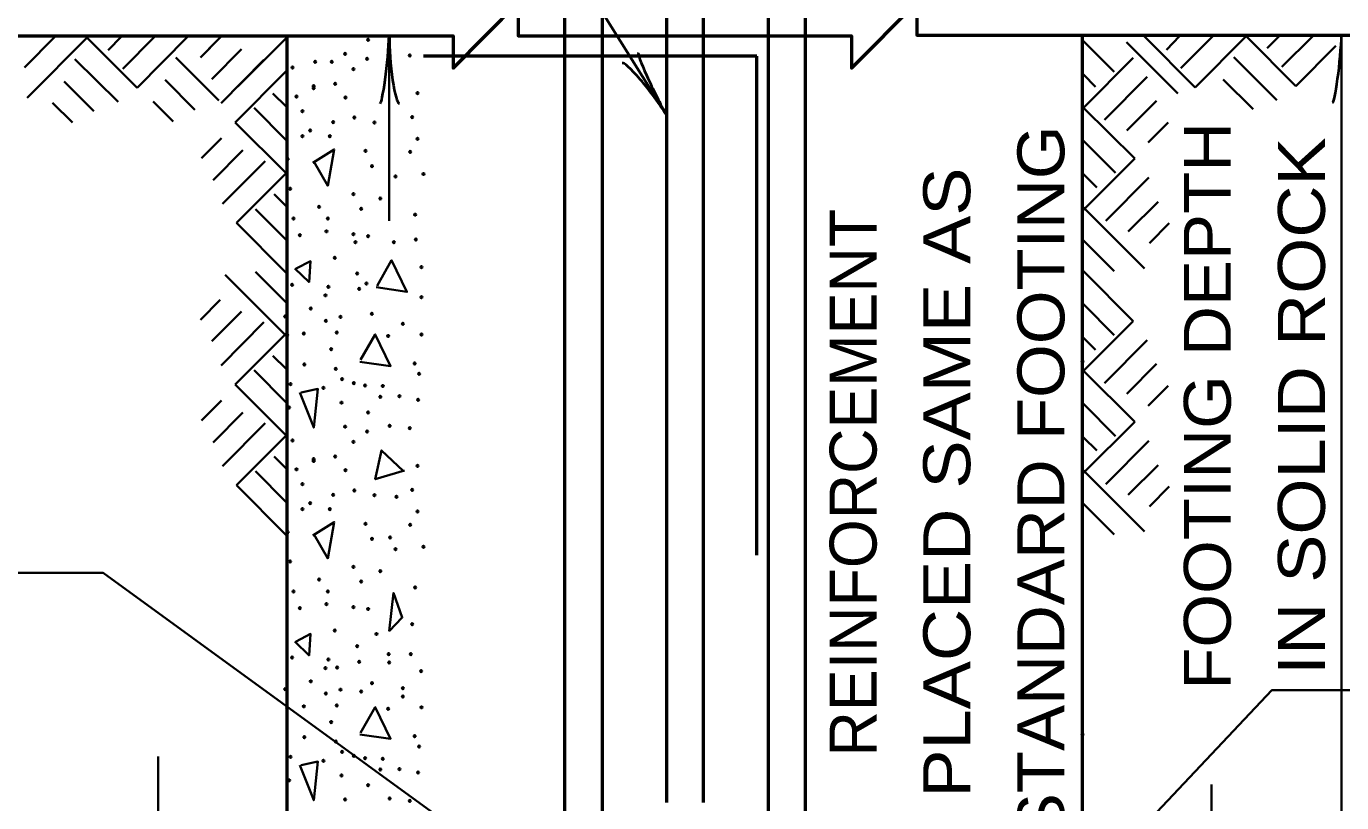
# Model space of a CAD drawing. Extents: x -39 to 816, y -16 to 528.
# Drawn here: x 422.4 to 490.2, y 435.9 to 475.9 of the extents above; entities that cross this region are included whole.
import ezdxf
from ezdxf.enums import TextEntityAlignment as Align

# ---------------------------------------------------------------- set-up
doc = ezdxf.new("R2010")
doc.units = 0
doc.header["$LTSCALE"] = 0.97
doc.layers.add('1', color=7, linetype='Continuous', lineweight=35)

msp = doc.modelspace()

# ---------------------------------------------------------------- linework, layer by layer
at = {"layer": '1', "lineweight": 53}
for p, q in [((450.1526, 483.0279), (450.1526, 432.0759)), ((452.0966, 483.0279), (452.0966, 432.0759)), ((460.6406, 483.0279), (460.6406, 432.0759)), ((462.5606, 483.0279), (462.5606, 432.0759)), ((455.4086, 478.2519), (455.4086, 435.8919)), ((457.3046, 478.2519), (457.3046, 435.8919)), ((435.8726, 423.9879), (435.8726, 475.3959)), ((476.8406, 423.9879), (476.8406, 475.4199)), ((460.0608, 474.3369), (442.9008, 474.3369)), ((460.0608, 448.6329), (460.0608, 474.3369))]:
    msp.add_line(p, q, dxfattribs=at)
at = {"layer": '1'}
for p, q in [((423.9206, 475.3479), (422.3366, 473.7639)), ((425.6246, 475.3479), (422.4806, 472.2039)), ((425.5046, 475.3479), (428.1446, 472.7079)), ((427.3286, 475.3479), (426.6566, 474.6519)), ((429.0566, 475.3479), (427.4006, 473.6919)), ((430.7606, 475.3479), (428.1446, 472.7079)), ((432.4166, 475.2999), (431.4086, 474.2679)), ((432.4646, 475.3479), (431.8406, 474.7239)), ((435.8966, 475.3479), (433.3286, 472.7799)), ((441.1286, 475.3959), (441.1286, 465.8679)), ((476.8886, 475.1199), (478.4726, 473.5359)), ((479.1115, 475.0579), (481.7515, 472.4179)), ((480.0086, 475.3719), (482.6486, 472.7319)), ((481.8326, 475.3719), (481.1606, 474.6759)), ((483.5606, 475.3719), (481.9046, 473.7159)), ((485.2646, 475.3719), (482.6486, 472.7319)), ((485.2646, 475.3719), (487.8326, 472.8039)), ((486.9686, 475.3719), (486.3446, 474.7479)), ((488.6966, 475.3719), (487.1126, 473.7879)), ((490.1846, 475.4199), (490.1846, 423.9879)), ((433.5206, 474.6999), (431.9846, 473.1639)), ((489.8961, 474.8674), (487.8326, 472.8039)), ((424.9286, 474.1959), (427.1606, 471.9879)), ((430.1366, 474.2679), (432.3446, 472.0599)), ((434.6726, 474.1479), (432.4646, 471.9159)), ((476.8886, 471.6879), (479.4566, 474.2559)), ((484.6406, 474.2919), (486.8486, 472.0839)), ((424.3766, 473.0439), (425.9126, 471.5079)), ((429.5846, 473.1159), (431.1206, 471.5799)), ((435.8246, 473.5719), (433.1846, 470.9319)), ((476.8886, 473.3919), (477.5126, 472.7679)), ((477.9686, 471.0639), (480.1766, 473.2719)), ((484.0886, 473.1399), (485.6246, 471.6039)), ((435.8246, 471.7479), (435.1286, 472.4199)), ((423.7766, 471.9399), (424.8086, 470.9319)), ((428.9606, 472.0119), (429.9926, 470.9799)), ((435.8246, 470.0199), (434.1686, 471.6759)), ((476.8886, 471.6879), (479.5286, 469.0719)), ((479.1206, 470.5119), (480.6566, 472.0479)), ((435.8246, 468.3159), (433.1846, 470.9319)), ((480.2246, 469.8879), (481.2566, 470.9199)), ((432.4886, 470.1159), (431.4566, 469.0839)), ((476.8886, 469.9839), (478.5446, 468.3279)), ((433.5926, 469.4919), (432.0566, 467.9559)), ((434.7446, 468.9399), (432.5366, 466.7319)), ((476.8886, 466.4319), (479.5286, 469.0719)), ((435.8246, 468.3159), (433.2566, 465.7479)), ((476.8886, 468.2559), (477.5846, 467.5839)), ((478.0406, 465.8559), (480.2486, 468.0879)), ((435.8246, 466.6119), (435.2006, 467.2359)), ((435.8246, 464.8839), (434.2406, 466.4679)), ((476.8886, 466.5519), (480.0326, 463.4079)), ((479.1926, 465.3039), (480.7286, 466.8399)), ((435.8246, 463.1799), (433.2566, 465.7479)), ((480.2966, 464.7039), (481.3046, 465.7359)), ((476.8886, 464.8479), (478.4726, 463.2639)), ((435.8246, 459.9399), (432.6806, 463.0839)), ((435.8246, 461.6439), (434.2406, 463.2279)), ((476.8886, 463.2639), (479.4566, 460.6959)), ((432.4166, 461.7879), (431.4086, 460.7559)), ((476.8886, 461.5599), (478.4726, 459.9759)), ((433.5206, 461.1879), (431.9846, 459.6519)), ((434.6726, 460.6359), (432.4646, 458.4039)), ((476.8886, 458.1279), (479.4566, 460.6959)), ((435.8246, 460.0599), (433.1846, 457.4199)), ((476.8886, 459.8319), (477.5126, 459.2079)), ((477.9686, 457.5039), (480.1766, 459.7119)), ((435.8246, 458.2359), (435.1286, 458.9079)), ((435.8246, 456.5079), (434.1686, 458.1639)), ((476.8886, 458.1279), (479.5286, 455.5119)), ((479.1206, 456.9519), (480.6566, 458.4879)), ((435.8246, 454.8039), (433.1846, 457.4199)), ((480.2246, 456.3279), (481.2566, 457.3599)), ((432.4886, 456.6039), (431.4566, 455.5719)), ((476.8886, 456.4239), (478.5446, 454.7679)), ((433.5926, 455.9799), (432.0566, 454.4439)), ((434.7446, 455.4279), (432.5366, 453.2199)), ((476.8886, 452.8719), (479.5286, 455.5119)), ((435.8246, 454.8039), (433.2566, 452.2359)), ((476.8886, 454.6959), (477.5846, 454.0239)), ((478.0406, 452.2959), (480.2486, 454.5279)), ((435.8246, 453.0999), (435.2006, 453.7239)), ((435.8246, 451.3719), (434.2406, 452.9559)), ((476.8886, 452.9919), (480.0326, 449.8479)), ((479.1926, 451.7439), (480.7286, 453.2799)), ((435.8246, 449.6679), (433.2566, 452.2359)), ((480.2966, 451.1439), (481.3046, 452.1759)), ((476.8886, 451.2879), (478.4726, 449.7039)), ((429.2246, 428.7399), (429.2246, 438.2679)), ((483.4886, 427.2999), (483.4886, 436.8279))]:
    msp.add_line(p, q, dxfattribs=at)
for points in [[(455.4086, 471.3159), (437.3846, 500.1399), (427.8086, 500.1399)], [(437.2406, 468.9159), (437.9606, 467.6679), (438.2966, 469.5399), (437.1926, 468.8439)], [(436.2566, 463.3959), (437.0006, 462.6999), (437.0726, 463.7799), (436.3286, 463.3959)], [(440.5046, 462.5079), (441.2486, 463.8279), (442.0406, 462.1959), (440.4566, 462.4359)], [(439.6406, 458.6919), (440.4086, 460.0119), (441.2006, 458.3799), (439.6166, 458.5959)], [(436.5206, 457.0119), (437.2406, 455.2119), (437.4566, 457.2039), (436.5926, 457.0119)], [(441.9206, 453.0039), (440.4086, 452.5479), (440.7206, 454.0359), (441.8486, 452.9799)], [(437.2406, 449.7159), (437.9606, 448.4679), (438.2966, 450.3399), (437.1926, 449.6439)], [(449.2166, 431.1159), (426.3926, 447.7239), (421.0166, 447.7239)], [(436.2566, 444.1959), (437.0006, 443.4759), (437.0726, 444.5799), (436.3286, 444.1959)], [(473.0246, 427.2999), (486.5984, 441.6829), (498.6932, 441.6829)], [(439.6406, 439.4919), (440.4086, 440.8119), (441.2006, 439.1799), (439.6166, 439.3959)], [(436.5206, 437.8119), (437.2406, 436.0119), (437.4566, 438.0039), (436.5926, 437.8119)]]:
    msp.add_lwpolyline(points, dxfattribs=at)
at = {"layer": '1', "lineweight": 53}
msp.add_lwpolyline([(419.0094, 475.3959), (444.4166, 475.3959), (444.4166, 473.7159), (447.7766, 477.0999), (447.7766, 475.3959), (464.9366, 475.3959), (464.9366, 473.7159), (468.2966, 477.0999), (468.2966, 475.4199), (493.9107, 475.4199)], dxfattribs=at)
at = {"layer": '1'}
msp.add_lwpolyline([(441.1286, 444.7239), (441.3446, 446.6919), (441.8006, 445.4199)], close=True, dxfattribs=at)
for centre in [(440.0375, 475.1906), (438.8504, 474.4585), (442.1843, 474.3828), (436.148, 473.7515), (437.3178, 474.053), (438.1675, 474.053), (439.2797, 473.6758), (439.9869, 474.2059), (438.3453, 472.9183), (436.3499, 472.2619), (437.2339, 472.7921), (437.2339, 472.6911), (442.5885, 472.4386), (438.8757, 472.2113), (436.653, 471.5043), (438.2442, 470.9489), (439.3303, 471.1761), (440.3659, 470.9236), (442.3106, 471.2014), (436.653, 470.2166), (437.0572, 470.5197), (438.0675, 470.2167), (442.5885, 470.0904), (435.8954, 469.0299), (439.9112, 469.4591), (442.2096, 469.4087), (440.2396, 468.6764), (442.8915, 468.2725), (436.0217, 467.5151), (441.4518, 468.1462), (439.2797, 467.2373), (440.669, 467.01), (437.5117, 466.5808), (439.6838, 466.4799), (442.4621, 466.1769), (436.1985, 465.975), (437.9664, 465.975), (436.5267, 465.1164), (437.8907, 465.3184), (439.2797, 465.1668), (440.0375, 465.066), (442.5037, 464.8953), (439.3881, 464.7536), (441.3707, 464.7536), (438.32, 463.9549), (442.7869, 463.4786), (439.4819, 463.1469), (436.1227, 462.5663), (437.9917, 462.4653), (439.5828, 462.3498), (439.9545, 462.6286), (437.8401, 462.0216), (442.7869, 461.9203), (435.7692, 460.9358), (437.0824, 461.3398), (437.8654, 460.7085), (438.6231, 460.9106), (440.2377, 461.0702), (436.7289, 460.0521), (438.421, 460.1027), (441.8308, 460.5571), (435.8701, 459.9764), (441.073, 459.9258), (442.7905, 460.0017), (438.1432, 459.2441), (436.7542, 458.4614), (438.3706, 458.2341), (442.437, 458.512), (476.8417, 458.6068), (436.047, 457.4514), (438.6988, 457.704), (439.305, 457.502), (439.8859, 457.3757), (440.7952, 457.3505), (442.6642, 457.9818), (437.7391, 457.2495), (440.669, 456.795), (441.654, 456.8203), (442.6137, 456.6436), (435.9711, 456.2395), (438.6736, 456.4921), (440.0375, 455.987), (441.1487, 455.3053), (438.8504, 455.2549), (439.9869, 455.0023), (442.1843, 455.1792), (436.148, 454.5478), (439.2797, 454.4722), (437.2339, 453.5885), (437.2339, 453.4875), (438.3453, 453.7147), (436.3499, 453.0583), (438.8757, 453.0077), (442.5885, 453.235), (436.653, 452.3007), (439.3303, 451.9725), (442.3106, 451.9978), (437.0572, 451.316), (438.2442, 451.7452), (440.3659, 451.72), (441.5024, 451.6443), (436.653, 451.0129), (438.0675, 451.0131), (442.5885, 450.8868), (439.9112, 450.2555), (442.2096, 450.2051), (435.8954, 449.8263), (440.2396, 449.4728), (441.174, 449.5487), (441.4518, 448.9426), (442.8915, 449.0689), (436.0217, 448.3115), (439.2797, 448.0337), (437.5117, 447.3772), (439.6838, 447.2762), (440.669, 447.8064), (436.1985, 446.7713), (437.9664, 446.7713), (442.4621, 446.9733), (436.5267, 445.9128), (437.8907, 446.1147), (439.2797, 445.9632), (440.0375, 445.8624), (438.32, 444.7513), (440.4668, 444.5746), (442.3106, 445.0797), (439.4819, 443.9433), (436.1227, 443.3627), (437.9917, 443.2617), (439.5828, 443.1462), (441.0982, 443.5394), (441.1278, 443.1086), (442.2349, 443.5394), (437.8401, 442.818), (438.4463, 442.8431), (442.7652, 442.6664), (435.7692, 441.7322), (437.0824, 442.1362), (440.2396, 442.0353), (441.8308, 441.7827), (437.8654, 441.5049), (438.6231, 441.707), (439.6838, 441.6059), (441.8308, 441.3535), (435.8701, 440.7728), (436.7289, 440.8485), (438.421, 440.899), (441.073, 440.7222), (442.7905, 440.7981), (438.1432, 440.0405), (436.7542, 439.2578), (438.3706, 439.0305), (442.437, 439.3083), (476.8417, 439.4032), (438.6988, 438.5004), (442.6642, 438.7782), (436.047, 438.2478), (437.7391, 438.0459), (439.305, 438.2984), (439.8859, 438.1721), (440.7952, 438.1468), (435.9711, 437.0359), (438.6736, 437.2884), (440.669, 437.5914), (441.654, 437.6167), (442.6137, 437.44), (440.0375, 436.7834), (438.8504, 436.0513), (441.1487, 436.1017), (442.1843, 435.9756)]:
    msp.add_circle(centre, 0.0504, dxfattribs=at)
at = {"layer": '1', "lineweight": 40}
for centre, major_axis, ratio, start_param, end_param in [((440.8699, 474.0347), (0.2125, 2.1246), 0.07063, 3.1407148, 5.41811), ((440.8699, 474.0347), (0.2125, 2.1246), 0.07063, 3.1407148, 5.41811), ((441.46, 474.0702), (-0.1889, 2.16), 0.122415, 0.8963533, 3.1415927), ((441.46, 474.0702), (-0.1889, 2.16), 0.122415, 0.8963533, 3.1415927), ((489.9343, 474.0725), (0.2125, 2.1246), 0.07063, 3.1407148, 5.41811), ((454.9128, 472.5926), (-0.9461, 1.9142), 0.07063, 6.2823074, 8.5597026), ((454.9128, 472.5926), (-0.9461, 1.9142), 0.07063, 6.2823074, 8.5597026), ((454.4311, 472.2497), (1.3052, -1.7314), 0.122415, 0.8963533, 3.1415927), ((454.4311, 472.2497), (1.3052, -1.7314), 0.122415, 0.8963533, 3.1415927)]:
    msp.add_ellipse(centre, major_axis=major_axis, ratio=ratio, start_param=start_param, end_param=end_param, dxfattribs=at)

# ---------------------------------------------------------------- texts
at = {"layer": '1'}
for s, width, p in [('STANDARD FOOTING', 1.1, (475.9046, 452.3872)), ('FOOTING DEPTH', 1.1, (484.4788, 456.3277)), ('IN SOLID ROCK', 1.15, (489.3268, 456.3088)), ('PLACED SAME AS', 1.15, (471.0566, 452.3752))]:
    msp.add_text(s, height=2.419, rotation=90, dxfattribs=dict(at, width=width)).set_placement(p, align=Align.CENTER)
msp.add_text('REINFORCEMENT', height=2.419, rotation=90, dxfattribs=at).set_placement((466.2326, 452.3706), align=Align.CENTER)

doc.saveas('drawing.dxf')
